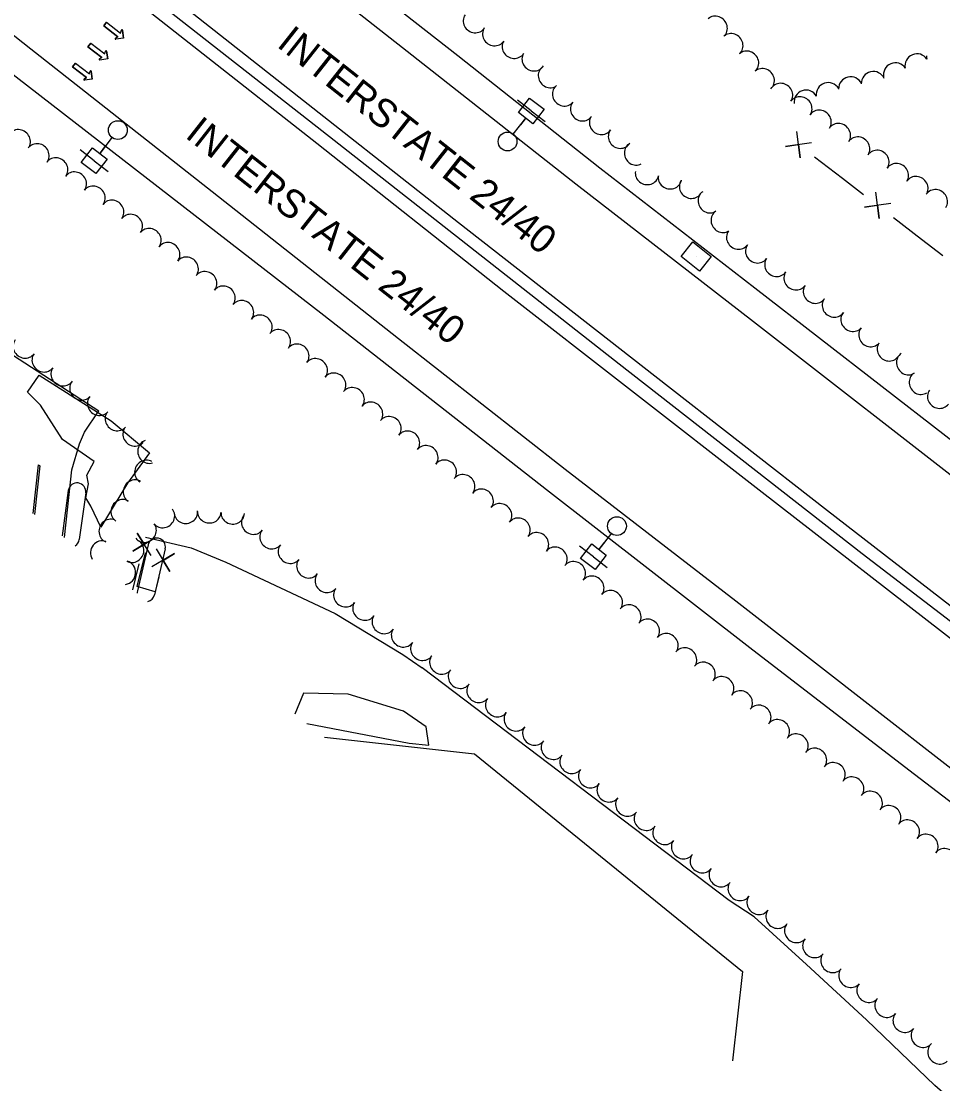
# Model space of a CAD drawing. Extents: x 1746010 to 1754829, y 655801 to 663091.
# Drawn here: x 1749324.1 to 1749716.7, y 660379.8 to 660832.4 of the extents above; entities that cross this region are included whole.
import ezdxf

# ---------------------------------------------------------------- set-up
doc = ezdxf.new("R2010")
doc.units = 0
for name, color, linetype in [('SURVEY - AERIAL SURVEY - Photo Control - Points - Locators', 7, 'Continuous'), ('SURVEY - AERIAL SURVEY - Photo Control - Points - Numbers', 7, 'Continuous'), ('SURVEY - CENTERLINE - Existing Roads - Development', 7, 'Continuous'), ('SURVEY - CENTERLINE - Existing Roads Curve Text', 7, 'Continuous'), ('SURVEY - CENTERLINE - Existing Roads Text', 7, 'Continuous'), ('SURVEY - CENTERLINE - Preliminary - Development', 7, 'Continuous'), ('SURVEY - CONTROL - Points - Numbers', 7, 'Continuous'), ('SURVEY - DRAINAGE - Area Shapes - Points - Elevations', 7, 'Continuous')]:
    doc.layers.add(name, color=color, linetype=linetype)

msp = doc.modelspace()

# ---------------------------------------------------------------- linework, layer by layer
at = {"layer": 'SURVEY - AERIAL SURVEY - Photo Control - Points - Locators'}
for points in [[(1749328.25, 660820.51), (1749265.45, 660870.2), (1749186.55, 660933.71), (1749132.73, 660977.41), (1749077.4, 661022.72), (1749061.25, 661035.93)], [(1749387.11, 660899.35), (1749486.53, 660821.3), (1749560.37, 660763.13), (1749636.02, 660704.45), (1749732.4, 660629.58), (1749833.07, 660551.99), (1749920.33, 660484.88), (1750008.5, 660418.55), (1750084.45, 660361.56), (1750166.82, 660299.99), (1750252.84, 660236.3), (1750339.47, 660172.61), (1750424.46, 660110.17), (1750505.09, 660051.79), (1750510.03, 660048.27)], [(1750422.34, 660058.69), (1750341.81, 660116.67), (1750243.85, 660188.2), (1750158.07, 660251.54), (1750079.76, 660310), (1749998.95, 660370.82), (1749924.19, 660427.29), (1749840.05, 660491.49), (1749747.97, 660561.59), (1749667.56, 660623.87), (1749593.96, 660681.21), (1749510.38, 660746.53), (1749431.04, 660809.06), (1749359.66, 660865.36)], [(1749353.21, 660856.72), (1749450.09, 660780.53), (1749529.69, 660717.36), (1749638.4, 660632.78), (1749725.25, 660565.49), (1749826.74, 660487.69), (1749908.21, 660425.76), (1750015.78, 660344.74), (1750134.74, 660255.49), (1750241.73, 660176.3), (1750327.29, 660113.27), (1750398.53, 660061.52)], [(1750309.34, 660072.12), (1750268.26, 660102.16), (1750202.16, 660151.04), (1750125.31, 660207.81), (1750054.71, 660260.76), (1749978.89, 660317.54), (1749904.25, 660374.13), (1749807.5, 660447.32), (1749742.59, 660496.65), (1749689.97, 660537.57), (1749628.45, 660585.34), (1749555.8, 660641.5), (1749484.89, 660697.07), (1749405.47, 660759.79), (1749328.25, 660820.51)], [(1750288.61, 660074.58), (1750206.58, 660134.59), (1750105.78, 660208.88), (1750014.16, 660277.34), (1749883.11, 660375.92), (1749790.93, 660445.43), (1749702.19, 660513.29), (1749634.54, 660565.49), (1749547.88, 660632.78), (1749453.06, 660707.08), (1749311.71, 660816.35)], [(1749238.62, 660736.41), (1749268.12, 660725.4), (1749317.94, 660691.81), (1749357.13, 660666.5)], [(1749345.74, 660641.35), (1749348.99, 660652.34), (1749351.04, 660657.38), (1749357.13, 660666.5)], [(1749342.52, 660612.48), (1749345.74, 660641.35)], [(1749377.12, 660612.67), (1749396.48, 660608.12), (1749411.33, 660602.04), (1749457.89, 660580.15), (1749486.62, 660562.6), (1749494.95, 660556.92)], [(1749949.53, 660142.04), (1749959.68, 660175.76), (1749908.29, 660214.04), (1749859.35, 660250.31), (1749801, 660295.27), (1749769.71, 660320.03), (1749752.54, 660333.06), (1749741.05, 660341.05), (1749737.1, 660343.79), (1749735.68, 660345.35), (1749737.91, 660357.63), (1749713.32, 660379), (1749684.22, 660407.06), (1749658.62, 660430.58), (1749636.39, 660450.84), (1749625.75, 660457.9), (1749494.88, 660556.97)]]:
    msp.add_lwpolyline(points, dxfattribs=at)
at = {"layer": 'SURVEY - AERIAL SURVEY - Photo Control - Points - Numbers'}
for points in [[(1750365.71, 660168.08), (1750350.37, 660178.69), (1750287.2, 660225.82), (1750205.37, 660286.01), (1750139.45, 660335.41), (1750086.68, 660374.49), (1749983.6, 660451.73), (1749923.2, 660497.58), (1749846.86, 660555.87), (1749777.3, 660609.82), (1749717.93, 660655.7), (1749636.62, 660718.64), (1749570.63, 660769.87), (1749510.15, 660817.71), (1749441.97, 660871.04), (1749371.15, 660927.67)], [(1749348.39, 660867.21), (1749450.14, 660787.41), (1749578.82, 660686.52), (1749682.3, 660605.65), (1749779.99, 660530.78), (1749879.01, 660455.62), (1749985.38, 660374.75), (1750084.31, 660300.06), (1750202.67, 660211.89), (1750354.74, 660100.39), (1750409.77, 660060.18)], [(1749329.15, 660622.74), (1749331.42, 660643.45), (1749332.07, 660643), (1749329.8, 660622.23)]]:
    msp.add_lwpolyline(points, dxfattribs=at)
at = {"layer": 'SURVEY - CENTERLINE - Existing Roads - Development'}
for p, q in [((1749344.19, 660632.57), (1749341.52, 660613.25)), ((1749351.62, 660631.54), (1749348.87, 660611.63)), ((1749378.14, 660609.4), (1749373.62, 660589.81)), ((1749385.45, 660607.71), (1749380.93, 660588.12))]:
    msp.add_line(p, q, dxfattribs=at)
for points in [[(1749660.79, 660780.65), (1749649.65, 660779.12), (1749655.18, 660779.91), (1749655.91, 660774.3), (1749654.53, 660785.46)], [(1749673.91, 660765.39), (1749662.02, 660774.53)], [(1749682.95, 660758.44), (1749673.91, 660765.39)], [(1749694.49, 660754.75), (1749683.35, 660753.22), (1749688.88, 660754.01), (1749689.61, 660748.4), (1749688.22, 660759.56)], [(1749707.61, 660739.49), (1749695.72, 660748.63)], [(1749716.65, 660732.54), (1749707.61, 660739.49)], [(1749355.16, 660644.9), (1749341.68, 660654.3), (1749332.37, 660668.82), (1749326.73, 660674.35), (1749331.75, 660681.58), (1749362.48, 660662.24), (1749378.71, 660648.54), (1749369.39, 660635.61), (1749357.99, 660616.87), (1749353.75, 660625.77), (1749351.7, 660629.38), (1749352.72, 660635.36), (1749352.05, 660639.02), (1749355.16, 660644.9)], [(1749379.43, 660604.82), (1749373.52, 660614.39), (1749376.49, 660609.65), (1749371.65, 660606.72), (1749381.29, 660612.49)], [(1749381.65, 660607.59), (1749387.42, 660597.95), (1749384.52, 660602.72), (1749389.38, 660605.6), (1749379.69, 660599.94)], [(1749373.45, 660591.65), (1749377.02, 660605.94), (1749377.27, 660605.86)], [(1749371.64, 660590.16), (1749374.33, 660601.23)], [(1749382.78, 660595.53), (1749381.2, 660589.37)], [(1749381.2, 660589.37), (1749373.45, 660591.65)], [(1749445.81, 660533.28), (1749489.38, 660524.9), (1749497.73, 660524.07), (1749496.56, 660531.78), (1749486.89, 660538.49), (1749463.42, 660545.74), (1749444.4, 660546.21), (1749440.66, 660537.23)], [(1749453.37, 660527.48), (1749517.21, 660520.31), (1749631.42, 660427.59), (1749627.14, 660389.52)]]:
    msp.add_lwpolyline(points, dxfattribs=at)
for centre, start, end in [((1749347.9, 660632.01), 352.1329, 172.1329), ((1749345.15, 660612.1), 302.3548, 352.1329), ((1749381.79, 660608.51), 346.9868, 166.9868), ((1749377.26, 660588.92), 166.9868, 183.1317), ((1749377.26, 660588.92), 281.9083, 346.9868)]:
    msp.add_arc(centre, 3.75, start, end, dxfattribs=at)
at = {"layer": 'SURVEY - CENTERLINE - Existing Roads Curve Text'}
for p, q in [((1749541.39, 660794.23), (1749535.46, 660798.82)), ((1749541.39, 660794.23), (1749547.32, 660789.64)), ((1749533.68, 660784.26), (1749539.01, 660791.14)), ((1749538.76, 660790.83), (1749536.8, 660788.3)), ((1749362.9, 660782.97), (1749357.58, 660776.08)), ((1749357.83, 660776.4), (1749359.78, 660778.93)), ((1749355.2, 660773), (1749349.26, 660777.59)), ((1749355.2, 660773), (1749361.13, 660768.41)), ((1749575.51, 660614.26), (1749570.21, 660607.36)), ((1749567.83, 660604.27), (1749561.88, 660608.85)), ((1749570.45, 660607.68), (1749572.4, 660610.21)), ((1749567.83, 660604.27), (1749573.77, 660599.7))]:
    msp.add_line(p, q, dxfattribs=at)
for points in [[(1749546.86, 660794.93), (1749542.09, 660788.76), (1749535.92, 660793.53), (1749540.7, 660799.7)], [(1749349.72, 660772.3), (1749354.5, 660778.47), (1749360.67, 660773.7), (1749355.89, 660767.53)], [(1749562.35, 660603.56), (1749567.12, 660609.74), (1749573.3, 660604.98), (1749568.54, 660598.8)]]:
    msp.add_lwpolyline(points, close=True, dxfattribs=at)
for centre in [(1749365.29, 660786.05), (1749531.29, 660781.18), (1749577.89, 660617.35)]:
    msp.add_circle(centre, 4, dxfattribs=at)
at = {"layer": 'SURVEY - CENTERLINE - Existing Roads Text'}
for centre, start, end in [((1749705.69, 660813.42), 34.2923, 191.0858), ((1749714.89, 660817.26), 175.7914, 191.0858), ((1749687.08, 660805.89), 24.6833, 181.4767), ((1749696.5, 660809.58), 34.2923, 191.0858), ((1749667.89, 660801.13), 30.1828, 186.9763), ((1749677.4, 660803.65), 24.6833, 181.4767), ((1749658.44, 660797.96), 30.1828, 186.9763)]:
    msp.add_arc(centre, 5.13, start, end, dxfattribs=at)
for centre, major_axis, start_param, end_param in [((1749517.31, 660832.31), (-4.15, 2.8), 0, 3.141593), ((1749620.08, 660829.74), (3.34, -3.72), 0, 3.141593), ((1749525.54, 660826.76), (-4.15, 2.8), 0, 3.141593), ((1749626.76, 660822.3), (3.34, -3.72), 0, 3.141593), ((1749533.88, 660821.34), (-4.23, 2.66), 0, 3.141593), ((1749633.44, 660814.86), (3.34, -3.72), 0, 3.141593), ((1749542.32, 660816.03), (-4.23, 2.66), 0, 3.141593), ((1749549.17, 660808.99), (-3.01, 4), 0, 3.141593), ((1749640.12, 660807.41), (3.34, -3.72), 0, 3.141593), ((1749647.86, 660801.17), (4.11, -2.85), 0, 3.141593), ((1749555.24, 660801.1), (-3.86, 3.18), 0, 3.141593), ((1749562.94, 660794.77), (-3.86, 3.18), 0, 3.141593), ((1749656.07, 660795.46), (4.11, -2.85), 0, 3.141593), ((1749664.28, 660789.75), (4.11, -2.85), 0, 3.141593), ((1749571.04, 660788.94), (-4.11, 2.85), 0, 3.141593), ((1749672.49, 660784.05), (4.11, -2.85), 0, 3.141593), ((1749323.16, 660781.46), (3.99, -3.01), 0, 3.141593), ((1749579.08, 660783.07), (-3.97, 3.04), 0, 3.141593), ((1749680.71, 660778.36), (4.11, -2.84), 0, 3.141593), ((1749331.13, 660775.45), (3.99, -3.01), 0, 3.141593), ((1749585.81, 660776.05), (-2.4, 4.39), 0, 3.141593), ((1749339.09, 660769.43), (3.99, -3.01), 0, 3.141593), ((1749688.94, 660772.68), (4.11, -2.84), 0, 3.141593), ((1749697.2, 660767.05), (4.15, -2.79), 0, 3.141593), ((1749347.05, 660763.42), (3.99, -3.01), 0, 3.141593), ((1749590.69, 660767.52), (-4.92, 0.92), 0, 3.141593), ((1749600.46, 660765.69), (-4.92, 0.92), 0, 3.141593), ((1749705.49, 660761.48), (4.15, -2.79), 0, 3.141593), ((1749355.01, 660757.4), (3.99, -3.01), 0, 3.141593), ((1749609.37, 660761.74), (-4.07, 2.9), 0, 3.141593), ((1749713.78, 660755.9), (4.15, -2.79), 0, 3.141593), ((1749362.97, 660751.38), (3.99, -3.01), 0, 3.141593), ((1749617.22, 660755.65), (-2.77, 4.16), 0, 3.141593), ((1749370.93, 660745.37), (3.99, -3.01), 0, 3.141593), ((1749622.75, 660747.32), (-2.77, 4.16), 0, 3.141593), ((1749378.89, 660739.35), (3.99, -3.01), 0, 3.141593), ((1749629.42, 660740.09), (-4.05, 2.93), 0, 3.141593), ((1749386.86, 660733.34), (3.99, -3.01), 0, 3.141593), ((1749637.52, 660734.23), (-4.05, 2.93), 0, 3.141593), ((1749394.72, 660727.17), (3.93, -3.09), 0, 3.141593), ((1749645.7, 660728.48), (-4.09, 2.87), 0, 3.141593), ((1749402.57, 660720.99), (3.93, -3.09), 0, 3.141593), ((1749653.89, 660722.74), (-4.11, 2.85), 0, 3.141593), ((1749410.42, 660714.81), (3.93, -3.09), 0, 3.141593), ((1749662.11, 660717.03), (-4.11, 2.85), 0, 3.141593), ((1749418.28, 660708.64), (3.93, -3.09), 0, 3.141593), ((1749670.2, 660711.15), (-4.01, 2.99), 0, 3.141593), ((1749426.13, 660702.46), (3.93, -3.09), 0, 3.141593), ((1749678.13, 660705.07), (-3.8, 3.25), 0, 3.141593), ((1749433.98, 660696.28), (3.93, -3.09), 0, 3.141593), ((1749685.73, 660698.57), (-3.8, 3.25), 0, 3.141593), ((1749325.56, 660693.71), (-4.02, 2.97), 0, 3.141593), ((1749441.84, 660690.1), (3.93, -3.09), 0, 3.141593), ((1749693.6, 660692.45), (-4.1, 2.86), 0, 3.141593), ((1749333.6, 660687.78), (-4.02, 2.97), 0, 3.141593), ((1749449.69, 660683.92), (3.93, -3.09), 0, 3.141593), ((1749701.73, 660686.7), (-2.72, 4.2), 0, 3.141593), ((1749341.64, 660681.84), (-4.02, 2.97), 0, 3.141593), ((1749457.54, 660677.75), (3.93, -3.09), 0, 3.141593), ((1749707.14, 660678.34), (-2.72, 4.2), 0, 3.141593), ((1749349.64, 660675.85), (-3.78, 3.27), 0, 3.141593), ((1749465.4, 660671.57), (3.93, -3.09), 0, 3.141593), ((1749715.03, 660672.3), (-4.01, 2.99), 0, 3.141593), ((1749357.2, 660669.31), (-3.78, 3.27), 0, 3.141593), ((1749473.25, 660665.39), (3.93, -3.09), 0, 3.141593), ((1749364.76, 660662.78), (-3.78, 3.27), 0, 3.141593), ((1749481.1, 660659.21), (3.93, -3.09), 0, 3.141593), ((1749372.31, 660656.24), (-3.78, 3.27), 0, 3.141593), ((1749488.96, 660653.03), (3.93, -3.09), 0, 3.141593), ((1749378.49, 660649.05), (-1.53, 4.76), 0, 3.141593), ((1749496.81, 660646.86), (3.93, -3.09), 0, 3.141593), ((1749377.22, 660640.48), (2.51, 4.33), 0, 3.141593), ((1749504.66, 660640.68), (3.93, -3.09), 0, 3.141593), ((1749512.52, 660634.5), (3.93, -3.09), 0, 3.141593), ((1749372.35, 660632.12), (2.65, 4.24), 0, 3.141593), ((1749520.37, 660628.32), (3.93, -3.09), 0, 3.141593), ((1749367.11, 660623.74), (2.65, 4.24), 0, 3.141593), ((1749528.22, 660622.14), (3.93, -3.09), 0, 3.141593), ((1749361.99, 660615.29), (1.84, 4.65), 0, 3.141593), ((1749384.64, 660621.43), (-3.92, -3.1), 0, 3.141593), ((1749394.29, 660623.17), (-4.96, -0.61), 0, 3.141593), ((1749404.23, 660623.37), (-4.99, 0.24), 0, 3.141593), ((1749414.22, 660622.9), (-4.99, 0.24), 0, 3.141593), ((1749422.79, 660618.64), (-3.92, 3.1), 0, 3.141593), ((1749536.07, 660615.96), (3.93, -3.09), 0, 3.141593), ((1749376.8, 660615.23), (-3.92, -3.1), 0, 3.141593), ((1749358.36, 660606.12), (1.84, 4.65), 0, 2.535454), ((1749430.63, 660612.44), (-3.92, 3.1), 0, 3.141593), ((1749543.93, 660609.79), (3.93, -3.09), 0, 3.141593), ((1749371.57, 660606.75), (-2.52, -4.32), 0, 3.141593), ((1749438.47, 660606.24), (-3.92, 3.1), 0, 3.141593), ((1749551.78, 660603.61), (3.93, -3.09), 0, 3.141593), ((1749368.15, 660597.47), (-1.13, -4.87), 0.329942, 3.141593), ((1749446.32, 660600.04), (-3.92, 3.1), 0, 3.141593), ((1749559.63, 660597.43), (3.93, -3.09), 0, 3.141593), ((1749454.16, 660593.84), (-3.92, 3.1), 0, 3.141593), ((1749567.49, 660591.25), (3.93, -3.09), 0, 3.141593), ((1749462.04, 660587.7), (-4.11, 2.85), 0, 3.141593), ((1749575.35, 660585.09), (3.96, -3.06), 0, 3.141593), ((1749470.25, 660582), (-4.11, 2.85), 0, 3.141593), ((1749583.26, 660578.98), (3.96, -3.06), 0, 3.141593), ((1749478.46, 660576.3), (-4.11, 2.85), 0, 3.141593), ((1749591.17, 660572.87), (3.96, -3.06), 0, 3.141593), ((1749486.67, 660570.6), (-4.11, 2.85), 0, 3.141593), ((1749599.07, 660566.77), (3.96, -3.06), 0, 3.141593), ((1749494.87, 660564.9), (-4.11, 2.85), 0, 3.141593), ((1749606.98, 660560.66), (3.96, -3.06), 0, 3.141593), ((1749502.97, 660559.06), (-3.97, 3.04), 0, 3.141593), ((1749614.89, 660554.55), (3.96, -3.06), 0, 3.141593), ((1749510.89, 660553.01), (-3.97, 3.04), 0, 3.141593), ((1749622.8, 660548.44), (3.96, -3.06), 0, 3.141593), ((1749518.81, 660546.96), (-3.97, 3.04), 0, 3.141593), ((1749526.73, 660540.9), (-3.97, 3.04), 0, 3.141593), ((1749630.71, 660542.34), (3.96, -3.06), 0, 3.141593), ((1749638.61, 660536.23), (3.96, -3.06), 0, 3.141593), ((1749534.66, 660534.85), (-3.97, 3.04), 0, 3.141593), ((1749646.52, 660530.12), (3.96, -3.06), 0, 3.141593), ((1749542.58, 660528.8), (-3.97, 3.04), 0, 3.141593), ((1749550.5, 660522.75), (-3.97, 3.04), 0, 3.141593), ((1749654.43, 660524.01), (3.96, -3.06), 0, 3.141593), ((1749662.34, 660517.91), (3.96, -3.06), 0, 3.141593), ((1749558.42, 660516.7), (-3.97, 3.04), 0, 3.141593), ((1749670.24, 660511.8), (3.96, -3.06), 0, 3.141593), ((1749566.34, 660510.65), (-3.97, 3.04), 0, 3.141593), ((1749574.26, 660504.59), (-3.97, 3.04), 0, 3.141593), ((1749678.15, 660505.69), (3.96, -3.06), 0, 3.141593), ((1749686.06, 660499.58), (3.96, -3.06), 0, 3.141593), ((1749582.18, 660498.54), (-3.97, 3.04), 0, 3.141593), ((1749693.97, 660493.48), (3.96, -3.06), 0, 3.141593), ((1749590.11, 660492.49), (-3.97, 3.04), 0, 3.141593), ((1749598.03, 660486.44), (-3.97, 3.04), 0, 3.141593), ((1749701.87, 660487.37), (3.96, -3.06), 0, 3.141593), ((1749709.78, 660481.26), (3.96, -3.06), 0, 3.141593), ((1749605.95, 660480.39), (-3.97, 3.04), 0, 3.141593), ((1749717.69, 660475.15), (3.96, -3.06), 0, 3.141593), ((1749613.94, 660474.41), (-4.03, 2.96), 0, 3.141593), ((1749622.01, 660468.49), (-4.03, 2.96), 0, 3.141593), ((1749630.07, 660462.58), (-4.03, 2.96), 0, 3.141593), ((1749638.14, 660456.67), (-4.03, 2.96), 0, 3.141593), ((1749646.2, 660450.75), (-4.03, 2.96), 0, 3.141593), ((1749654.15, 660444.7), (-3.85, 3.19), 0, 3.141593), ((1749661.85, 660438.32), (-3.85, 3.19), 0, 3.141593), ((1749669.54, 660431.95), (-3.85, 3.19), 0, 3.141593), ((1749677.24, 660425.58), (-3.85, 3.19), 0, 3.141593), ((1749684.94, 660419.2), (-3.85, 3.19), 0, 3.141593), ((1749692.63, 660412.83), (-3.85, 3.19), 0, 3.141593), ((1749700.33, 660406.45), (-3.85, 3.19), 0, 3.141593), ((1749708.02, 660400.08), (-3.85, 3.19), 0, 3.141593), ((1749715.08, 660393.01), (-3.46, 3.61), 0, 3.141593)]:
    msp.add_ellipse(centre, major_axis=major_axis, ratio=0.940188, start_param=start_param, end_param=end_param, dxfattribs=at)
at = {"layer": 'SURVEY - CENTERLINE - Preliminary - Development'}
msp.add_line((1749611.6, 660732.2), (1749611.6, 660732.2), dxfattribs=at)
msp.add_lwpolyline([(1749605.2, 660732.21), (1749610.22, 660738.45), (1749618.01, 660732.18), (1749612.99, 660725.94), (1749605.2, 660732.21)], dxfattribs=at)
at = {"layer": 'SURVEY - DRAINAGE - Area Shapes - Points - Elevations'}
for p, q in [((1749359.3, 660830.4), (1749360.5, 660831.96)), ((1749360.5, 660831.96), (1749359.3, 660830.4)), ((1749365.28, 660825.83), (1749359.3, 660830.4)), ((1749359.3, 660830.4), (1749365.28, 660825.83)), ((1749360.5, 660831.96), (1749366.48, 660827.39)), ((1749360.5, 660831.96), (1749366.48, 660827.39)), ((1749364.22, 660825.21), (1749365.28, 660825.83)), ((1749365.28, 660825.83), (1749364.22, 660825.21)), ((1749367.72, 660825.2), (1749364.37, 660824.76)), ((1749367.72, 660825.2), (1749364.37, 660824.76)), ((1749366.48, 660827.39), (1749366.79, 660828.58)), ((1749366.48, 660827.39), (1749366.79, 660828.58)), ((1749367.27, 660828.55), (1749367.72, 660825.2)), ((1749367.72, 660825.2), (1749367.27, 660828.55)), ((1749352.55, 660821.55), (1749353.74, 660823.12)), ((1749353.74, 660823.12), (1749352.55, 660821.55)), ((1749358.53, 660816.98), (1749352.55, 660821.55)), ((1749352.55, 660821.55), (1749358.53, 660816.98)), ((1749353.74, 660823.12), (1749359.72, 660818.55)), ((1749353.74, 660823.12), (1749359.72, 660818.55)), ((1749359.72, 660818.55), (1749360.04, 660819.74)), ((1749359.72, 660818.55), (1749360.04, 660819.74)), ((1749360.52, 660819.71), (1749360.97, 660816.36)), ((1749360.97, 660816.36), (1749360.52, 660819.71)), ((1749357.46, 660816.37), (1749358.53, 660816.98)), ((1749358.53, 660816.98), (1749357.46, 660816.37)), ((1749360.97, 660816.36), (1749357.62, 660815.91)), ((1749360.97, 660816.36), (1749357.62, 660815.91)), ((1749345.99, 660812.96), (1749347.18, 660814.53)), ((1749347.18, 660814.53), (1749345.99, 660812.96)), ((1749351.96, 660808.39), (1749345.99, 660812.96)), ((1749345.99, 660812.96), (1749351.96, 660808.39)), ((1749347.18, 660814.53), (1749353.16, 660809.96)), ((1749347.18, 660814.53), (1749353.16, 660809.96)), ((1749353.16, 660809.96), (1749353.47, 660811.15)), ((1749353.16, 660809.96), (1749353.47, 660811.15)), ((1749353.96, 660811.12), (1749354.4, 660807.77)), ((1749354.4, 660807.77), (1749353.96, 660811.12)), ((1749350.9, 660807.78), (1749351.96, 660808.39)), ((1749351.96, 660808.39), (1749350.9, 660807.78)), ((1749354.4, 660807.77), (1749351.05, 660807.32)), ((1749354.4, 660807.77), (1749351.05, 660807.32))]:
    msp.add_line(p, q, dxfattribs=at)
for centre, start, end in [((1749367.03, 660828.52), 7.6227, 165.1159), ((1749367.03, 660828.52), 7.6227, 165.1159), ((1749364.34, 660825), 120.1744, 277.6227), ((1749364.34, 660825), 120.1744, 277.6227), ((1749360.27, 660819.67), 7.6227, 165.1159), ((1749360.27, 660819.67), 7.6227, 165.1159), ((1749357.59, 660816.16), 120.1744, 277.6227), ((1749357.59, 660816.16), 120.1744, 277.6227), ((1749353.71, 660811.08), 7.6227, 165.1159), ((1749353.71, 660811.08), 7.6227, 165.1159), ((1749351.02, 660807.56), 120.1744, 277.6227), ((1749351.02, 660807.56), 120.1744, 277.6227)]:
    msp.add_arc(centre, 0.246, start, end, dxfattribs=at)

# ---------------------------------------------------------------- texts
at = {"layer": 'SURVEY - CONTROL - Points - Numbers'}
for rotation, p in [(321.7378, (1749432.56, 660821.87)), (321.8204, (1749393.5, 660783.19))]:
    msp.add_text('INTERSTATE 24/40', height=12, rotation=rotation, dxfattribs=at).set_placement(p)

doc.saveas('drawing.dxf')
